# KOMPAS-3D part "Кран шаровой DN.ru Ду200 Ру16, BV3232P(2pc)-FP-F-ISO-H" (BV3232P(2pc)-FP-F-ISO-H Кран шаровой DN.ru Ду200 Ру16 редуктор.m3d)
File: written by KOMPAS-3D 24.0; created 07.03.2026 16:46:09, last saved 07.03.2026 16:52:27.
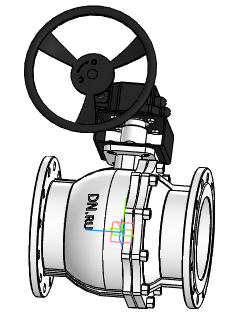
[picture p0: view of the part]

Document properties: Автор: R2D2; Полное имя файла: BV3232P(2pc)-FP-F-ISO-H Кран шаровой DN.ru Ду200 Ру16 редуктор.cdw

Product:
- Part/product: Кран шаровой DN.ru Ду200 Ру16  | designation BV3232P(2pc)-FP-F-ISO-H
    Масса: 72
    Раздел спецификации: Прочие изделия
    Форматы листов документа: A2
    Примечание: D160-22176

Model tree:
1. Операция без истории:1

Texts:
  BV3232P(2pc)-FP-F-ISO-H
